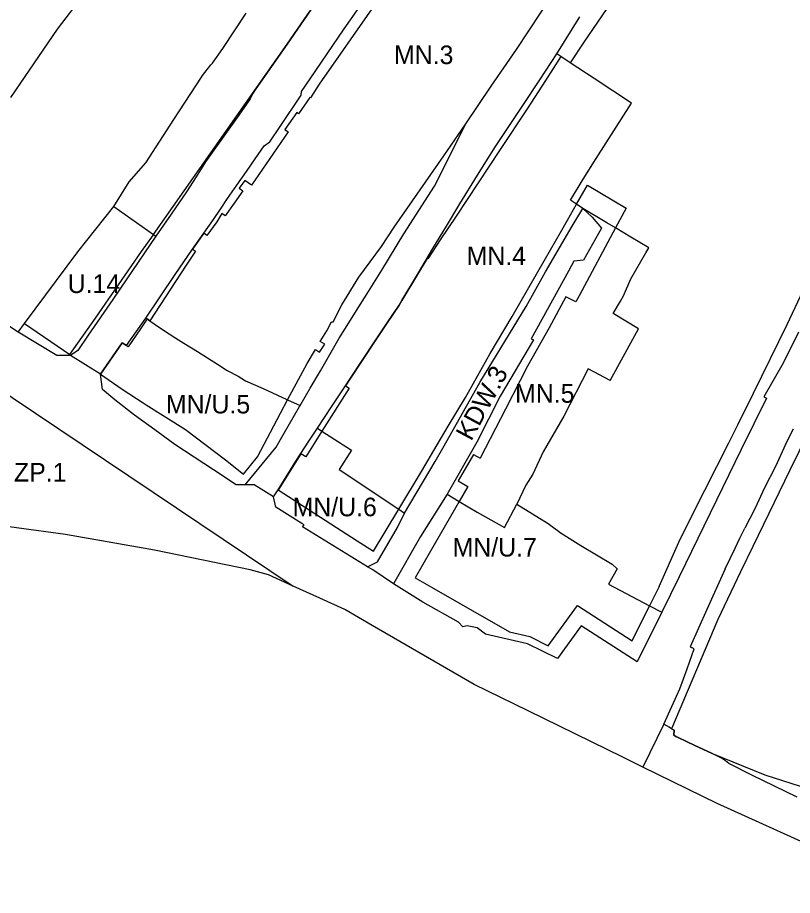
# Model space of a CAD drawing. Extents: x 7425067 to 7426806, y 5549054 to 5550619.
# Drawn here: x 7425448.3 to 7425656.7, y 5549710.3 to 5549946.2 of the extents above; entities that cross this region are included whole.
import ezdxf

# ---------------------------------------------------------------- set-up
doc = ezdxf.new("R2010")
doc.units = 0
for name, color, linetype in [('LIN_Linia Zabudowy Nieprzekraczalna', 7, 'Continuous'), ('LIN_linie_rozgraniczajace', 7, 'Continuous'), ('TXT_Oznaczenia_przeznaczen', 7, 'Continuous')]:
    doc.layers.add(name, color=color, linetype=linetype)

msp = doc.modelspace()

# ---------------------------------------------------------------- linework, layer by layer
at = {"layer": 'LIN_Linia Zabudowy Nieprzekraczalna'}
for points in [[(7425606.5552, 5550040.5472), (7425601.53, 5550033.23), (7425596.51, 5550025.92), (7425591.51, 5550018.64), (7425591.6694, 5550018.5304), (7425591.189, 5550017.8631), (7425586.63, 5550011.53), (7425580.79, 5550003.59), (7425574.84, 5549995.3), (7425575.473, 5549994.8457), (7425546.1246, 5549952.0475), (7425544.2494, 5549949.4263), (7425529.4643, 5549928.2635), (7425527.0756, 5549924.5966), (7425526.94, 5549924.69), (7425523.91, 5549920.31), (7425523.42, 5549920.65), (7425520.23, 5549916.11), (7425521.1342, 5549915.4829), (7425511.2359, 5549901.1957), (7425509.48, 5549902.41)], [(7425484.89, 5549887.86), (7425484.9072, 5549887.8845), (7425520.8, 5549939.01), (7425528.21, 5549949.7), (7425536.13, 5549960.83), (7425537.865, 5549963.3932), (7425543.4, 5549971.57), (7425551.62, 5549983.77), (7425559, 5549994.51), (7425566.23, 5550005.14), (7425570.21, 5550010.81), (7425573.53, 5550015.83), (7425576.29, 5550019.865), (7425579.04, 5550023.905)], [(7425562.96, 5549909.02), (7425568.86, 5549917.69), (7425575.69, 5549927.8), (7425582.5, 5549937.65), (7425585.82, 5549942.63), (7425589.14, 5549947.61), (7425589.3604, 5549947.9398), (7425595.33, 5549956.85), (7425600.34, 5549964.32), (7425605.32, 5549971.85), (7425606.075, 5549973.045), (7425606.83, 5549974.24), (7425608.59, 5549976.71), (7425613.61, 5549984.28), (7425616.08, 5549988.06), (7425618.55, 5549991.84), (7425620.06, 5549994.22), (7425621.56, 5549996.38), (7425626.76, 5550004.31)], [(7425607.9586, 5549950.3857), (7425600.624, 5549939.5493), (7425596.9747, 5549934.0514)], [(7425596.9747, 5549934.0514), (7425594.4146, 5549935.7314), (7425590.31, 5549929.31)], [(7425590.31, 5549929.31), (7425585.42, 5549921.66), (7425578.08, 5549910.74)], [(7425655.2768, 5549863.7294), (7425662.3503, 5549878.7355), (7425665.1746, 5549884.5158), (7425674.3584, 5549902.7629), (7425678.6779, 5549911.0696), (7425680.8016, 5549915.0743), (7425683.7745, 5549920.5636), (7425688.8399, 5549929.4585)], [(7425578.08, 5549910.74), (7425566.3, 5549892.86)], [(7425546.21, 5549884.66), (7425549.63, 5549889.86), (7425562.96, 5549909.02)], [(7425509.48, 5549902.41), (7425507.97, 5549900.35), (7425508.92, 5549899.61), (7425506.59, 5549896.34), (7425504.12, 5549892.89), (7425503.24, 5549893.56), (7425501.88, 5549891.31), (7425499.22, 5549887.64), (7425498.42, 5549888.23), (7425496.91, 5549886.115), (7425495.4, 5549884)], [(7425596.23, 5549891.77), (7425598.6683, 5549896.0411), (7425601.5888, 5549901.157), (7425611.9921, 5549894.9537)], [(7425611.9921, 5549894.9537), (7425609.1429, 5549889.6669), (7425599.32, 5549871.44), (7425598.42, 5549869.77), (7425595.81, 5549871.17)], [(7425556.93, 5549824.24), (7425561.17, 5549831.4), (7425564.1326, 5549836.403), (7425568.75, 5549844.11), (7425575.39, 5549855.96), (7425581.37, 5549865.85), (7425590.35, 5549881.47), (7425594.3076, 5549888.4025), (7425596.23, 5549891.77)], [(7425566.3, 5549892.86), (7425562.02, 5549886.44), (7425558.6225, 5549881.3438)], [(7425450.1963, 5549863.9878), (7425462.43, 5549855.62), (7425469.26, 5549865.41), (7425481.65, 5549883.35), (7425484.89, 5549887.86)], [(7425495.4, 5549884), (7425496.17, 5549883.43), (7425493.67, 5549879.62), (7425483.8994, 5549864.7296)], [(7425530.93, 5549858.45), (7425529.73, 5549859.19), (7425531.49, 5549861.99), (7425532.75, 5549864.44), (7425533.23, 5549864.42), (7425535.51, 5549869.03), (7425540.12, 5549876.43), (7425546.21, 5549884.66)], [(7425558.46, 5549881.44), (7425556.1545, 5549877.6482), (7425555.865, 5549877.165), (7425551.68, 5549870.18), (7425550.95, 5549868.96), (7425547.71, 5549864.135), (7425544.47, 5549859.31), (7425537.71, 5549849.04), (7425536.56, 5549847.28), (7425537.4818, 5549846.5976)], [(7425558.6225, 5549881.3438), (7425558.46, 5549881.44)], [(7425683.144, 5549879.4729), (7425674.6885, 5549862.4106), (7425668.0393, 5549848.9323), (7425663.2786, 5549839.311), (7425655.9796, 5549824.5332), (7425648.9293, 5549809.9832), (7425646.0622, 5549804.0686), (7425642.7058, 5549797.2362), (7425636.6761, 5549784.4652)], [(7425595.81, 5549871.17), (7425591.32, 5549862.78), (7425585.47, 5549852.55), (7425579.51, 5549840.95), (7425572.7321, 5549827.7581)], [(7425483.8994, 5549864.7296), (7425483.2128, 5549865.2121), (7425481.38, 5549862.55), (7425478.0556, 5549857.7212)], [(7425642.0429, 5549836.7222), (7425646.2851, 5549845.2863), (7425655.262, 5549863.6867), (7425655.2768, 5549863.7294)], [(7425478.0556, 5549857.7212), (7425477.6, 5549858.05), (7425476.5, 5549858.76), (7425470.6, 5549850.39)], [(7425493.45, 5549835.54), (7425504.29, 5549827.38), (7425509.12, 5549823.46), (7425512.84, 5549828.17), (7425519.03, 5549839.89), (7425520.9639, 5549843.5063), (7425526.18, 5549853.26), (7425528.45, 5549856.97), (7425529.57, 5549856.27), (7425530.93, 5549858.45)], [(7425470.6, 5549850.39), (7425476.47, 5549846.32), (7425482.11, 5549842.65), (7425482.91, 5549842.17), (7425493.45, 5549835.54)], [(7425537.4818, 5549846.5976), (7425530.1719, 5549835.0691), (7425528.08, 5549831.77), (7425525.81, 5549828.19), (7425524.54, 5549828.95), (7425518.51, 5549819.38)], [(7425626.1923, 5549805.2702), (7425629.9496, 5549812.8357), (7425639.6477, 5549831.8819), (7425642.0429, 5549836.7222)], [(7425570.94, 5549828.8), (7425566.8, 5549821.68)], [(7425570.94, 5549828.8), (7425572.7321, 5549827.7581)], [(7425544.0346, 5549802.8073), (7425550.8242, 5549814.0918), (7425556.93, 5549824.24)], [(7425569.4137, 5549820.2035), (7425569.3949, 5549820.171), (7425567.1006, 5549816.1863), (7425559.41, 5549802.83), (7425555.27, 5549795.64)], [(7425566.8, 5549821.68), (7425569.3949, 5549820.171)], [(7425518.42, 5549819.31), (7425539.7, 5549805.6), (7425544.0346, 5549802.8073)], [(7425620.8453, 5549793.314), (7425626.1923, 5549805.2702)], [(7425555.27, 5549795.64), (7425559.65, 5549793.11), (7425567.02, 5549788.89), (7425580.6308, 5549781.0966)], [(7425620.8453, 5549793.314), (7425618.2934, 5549788.1268)], [(7425591.0582, 5549777.4058), (7425598.9295, 5549788.1676), (7425613.6401, 5549778.6681)], [(7425613.6401, 5549778.6681), (7425618.2934, 5549788.1268)], [(7425636.6761, 5549784.4652), (7425624.1991, 5549755.0945)], [(7425580.6308, 5549781.0966), (7425586.1149, 5549779.8371), (7425591.0582, 5549777.4058)], [(7425624.1991, 5549755.0945), (7425624.94, 5549754.67), (7425624.79, 5549753.35), (7425625.375, 5549753.025), (7425625.96, 5549752.7), (7425630.45, 5549750.59), (7425634.94, 5549748.48), (7425649.28, 5549742.72), (7425658.83, 5549739.66), (7425672.26, 5549735.38), (7425680.88, 5549732.76), (7425701.88, 5549726.85)]]:
    msp.add_lwpolyline(points, dxfattribs=at)
at = {"layer": 'LIN_linie_rozgraniczajace'}
for points in [[(7425472.43, 5549960.77), (7425459.01, 5549943.13)], [(7425528.21, 5549949.7), (7425520.8, 5549939.01)], [(7425536.19, 5549943.2), (7425540.21, 5549948.92)], [(7425585.82, 5549942.63), (7425589.14, 5549947.61)], [(7425503.53, 5549937.93), (7425509.79, 5549947.39)], [(7425593.35, 5549936.43), (7425599.57, 5549946.4)], [(7425459.01, 5549943.13), (7425446.415, 5549924.73)], [(7425531.595, 5549936.465), (7425536.19, 5549943.2)], [(7425582.5, 5549937.65), (7425585.82, 5549942.63)], [(7425520.8, 5549939.01), (7425512.41, 5549927.03)], [(7425500.75, 5549933.94), (7425503.53, 5549937.93)], [(7425527, 5549929.73), (7425531.595, 5549936.465)], [(7425575.69, 5549927.8), (7425582.5, 5549937.65)], [(7425588.775, 5549929.505), (7425593.35, 5549936.43)], [(7425603.4, 5549929.835), (7425596.9747, 5549934.0514), (7425594.4146, 5549935.7314), (7425593.35, 5549936.43)], [(7425498.06, 5549930.65), (7425500.32, 5549933.47)], [(7425500.32, 5549933.47), (7425500.75, 5549933.94)], [(7425490.37, 5549918.8), (7425497.78, 5549930.21)], [(7425497.78, 5549930.21), (7425498.06, 5549930.65)], [(7425525.835, 5549928.025), (7425527, 5549929.73)], [(7425584.2, 5549922.58), (7425588.775, 5549929.505)], [(7425613.45, 5549923.24), (7425603.4, 5549929.835)], [(7425512.41, 5549927.03), (7425511.54, 5549925.72)], [(7425524.67, 5549926.32), (7425525.835, 5549928.025)], [(7425568.86, 5549917.69), (7425575.69, 5549927.8)], [(7425510.91, 5549924.4), (7425507.87, 5549919.98)], [(7425511.54, 5549925.72), (7425510.91, 5549924.4)], [(7425518.98, 5549916.93), (7425524.58, 5549925.38)], [(7425524.58, 5549925.38), (7425524.67, 5549926.32)], [(7425576.83, 5549911.52), (7425584.2, 5549922.58)], [(7425608.68, 5549915.78), (7425613.45, 5549923.24)], [(7425507.87, 5549919.98), (7425503.385, 5549913.695)], [(7425482.79, 5549907.13), (7425490.37, 5549918.8)], [(7425516.16, 5549912.83), (7425518.98, 5549916.93)], [(7425560.44, 5549900.91), (7425568.86, 5549917.69)], [(7425603.91, 5549908.32), (7425608.68, 5549915.78)], [(7425503.385, 5549913.695), (7425498.9, 5549907.41)], [(7425514.62, 5549911.72), (7425516.16, 5549912.83)], [(7425512.24, 5549908.275), (7425514.62, 5549911.72)], [(7425572.05, 5549903.815), (7425576.83, 5549911.52)], [(7425509.86, 5549904.83), (7425512.24, 5549908.275)], [(7425600.45, 5549902.745), (7425603.91, 5549908.32)], [(7425478.38, 5549902.07), (7425482.79, 5549907.13)], [(7425498.9, 5549907.41), (7425496.325, 5549903.395)], [(7425496.325, 5549903.395), (7425493.75, 5549899.38)], [(7425507.34, 5549901.185), (7425509.86, 5549904.83)], [(7425567.27, 5549896.11), (7425572.05, 5549903.815)], [(7425596.99, 5549897.17), (7425600.45, 5549902.745)], [(7425474.22, 5549895.44), (7425478.38, 5549902.07)], [(7425504.82, 5549897.54), (7425507.34, 5549901.185)], [(7425552.23, 5549888.05), (7425560.44, 5549900.91)], [(7425493.75, 5549899.38), (7425489.65, 5549893.405)], [(7425502.9, 5549894.755), (7425504.82, 5549897.54)], [(7425563.66, 5549890.13), (7425567.27, 5549896.11)], [(7425600.35, 5549894.91), (7425598.6683, 5549896.0411), (7425596.99, 5549897.17)], [(7425464.52, 5549883.22), (7425474.22, 5549895.44)], [(7425474.22, 5549895.44), (7425484.9072, 5549887.8845), (7425485.55, 5549887.43)], [(7425489.65, 5549893.405), (7425485.55, 5549887.43)], [(7425500.98, 5549891.97), (7425502.9, 5549894.755)], [(7425597.46, 5549890.14), (7425600.35, 5549894.91)], [(7425600.35, 5549894.91), (7425602.85, 5549892.6)], [(7425606.815, 5549891.055), (7425600.35, 5549894.91)], [(7425498.42, 5549888.23), (7425500.98, 5549891.97)], [(7425602.85, 5549892.6), (7425605.38, 5549889.59)], [(7425613.28, 5549887.2), (7425609.1429, 5549889.6669), (7425606.815, 5549891.055)], [(7425560.05, 5549884.15), (7425563.66, 5549890.13)], [(7425590.3, 5549877.89), (7425597.46, 5549890.14)], [(7425605.38, 5549889.59), (7425600.53, 5549881.02)], [(7425485.55, 5549887.43), (7425477.73, 5549876.01)], [(7425496.91, 5549886.115), (7425498.42, 5549888.23)], [(7425546.28, 5549878.3), (7425552.23, 5549888.05)], [(7425618.14, 5549884.3), (7425613.28, 5549887.2)], [(7425490.75, 5549877.19), (7425495.4, 5549884)], [(7425495.4, 5549884), (7425496.91, 5549886.115)], [(7425555.865, 5549877.165), (7425556.1545, 5549877.6482), (7425560.05, 5549884.15)], [(7425617.28, 5549882.98), (7425618.14, 5549884.3)], [(7425448.47, 5549861.67), (7425450.1963, 5549863.9878), (7425464.52, 5549883.22)], [(7425613.22, 5549875.96), (7425617.28, 5549882.98)], [(7425597.93, 5549880.73), (7425596.47, 5549878.03)], [(7425600.53, 5549881.02), (7425597.93, 5549880.73)], [(7425482.86, 5549865.46), (7425490.75, 5549877.19)], [(7425542.675, 5549872.555), (7425546.28, 5549878.3)], [(7425551.68, 5549870.18), (7425555.865, 5549877.165)], [(7425585.07, 5549868.55), (7425590.3, 5549877.89)], [(7425596.47, 5549878.03), (7425586.49, 5549859.84)], [(7425477.73, 5549876.01), (7425473.925, 5549870.475)], [(7425611.29, 5549871.39), (7425613.22, 5549875.96)], [(7425539.07, 5549866.81), (7425542.675, 5549872.555)], [(7425448.47, 5549861.67), (7425433.63, 5549871.43)], [(7425473.925, 5549870.475), (7425467.31, 5549860.84)], [(7425550.95, 5549868.96), (7425551.68, 5549870.18)], [(7425608.53, 5549866.71), (7425610.49, 5549870.01)], [(7425610.49, 5549870.01), (7425611.29, 5549871.39)], [(7425547.71, 5549864.135), (7425550.95, 5549868.96)], [(7425572.65, 5549848.14), (7425585.07, 5549868.55)], [(7425477.6, 5549858.05), (7425482.86, 5549865.46)], [(7425482.86, 5549865.46), (7425483.2128, 5549865.2121), (7425483.8994, 5549864.7296), (7425485.08, 5549863.9)], [(7425536.955, 5549863.425), (7425539.07, 5549866.81)], [(7425615.36, 5549862.59), (7425608.53, 5549866.71)], [(7425485.08, 5549863.9), (7425487.27, 5549862.35)], [(7425534.84, 5549860.04), (7425536.955, 5549863.425)], [(7425544.47, 5549859.31), (7425547.71, 5549864.135)], [(7425458.92, 5549855.37), (7425448.47, 5549861.67)], [(7425467.31, 5549860.84), (7425464.5, 5549856.74)], [(7425487.27, 5549862.35), (7425490.875, 5549860.045)], [(7425607.66, 5549848.67), (7425615.36, 5549862.59)], [(7425658.37, 5549861.7), (7425654.19, 5549853.35)], [(7425470.6, 5549850.39), (7425476.5, 5549858.76)], [(7425476.5, 5549858.76), (7425477.6, 5549858.05)], [(7425490.875, 5549860.045), (7425493.02, 5549858.68)], [(7425493.02, 5549858.68), (7425496.695, 5549856.435)], [(7425532.3, 5549855.65), (7425534.84, 5549860.04)], [(7425537.71, 5549849.04), (7425544.47, 5549859.31)], [(7425587.04, 5549859.59), (7425578.16, 5549844.45)], [(7425586.49, 5549859.84), (7425587.04, 5549859.59)], [(7425464.5, 5549856.74), (7425462.58, 5549855.42)], [(7425496.695, 5549856.435), (7425502.085, 5549853.045)], [(7425529.76, 5549851.26), (7425532.3, 5549855.65)], [(7425462.58, 5549855.42), (7425458.92, 5549855.37)], [(7425470.6, 5549850.39), (7425462.58, 5549855.42)], [(7425654.19, 5549853.35), (7425649.06, 5549844.26)], [(7425502.085, 5549853.045), (7425504.66, 5549851.36)], [(7425504.66, 5549851.36), (7425507.62, 5549849.83)], [(7425527.05, 5549846.615), (7425529.76, 5549851.26)], [(7425601.82, 5549851.83), (7425595.23, 5549839.09)], [(7425607.66, 5549848.67), (7425601.82, 5549851.83)], [(7425471.16, 5549846.24), (7425470.6, 5549850.39)], [(7425507.62, 5549849.83), (7425509.67, 5549848.61)], [(7425509.67, 5549848.61), (7425514.38, 5549846.5)], [(7425536.56, 5549847.28), (7425537.71, 5549849.04)], [(7425440.5058, 5549848.2743), (7425522.4788, 5549793.4392)], [(7425474.5, 5549843.44), (7425471.16, 5549846.24)], [(7425514.38, 5549846.5), (7425520.78, 5549843.59)], [(7425524.34, 5549841.97), (7425527.05, 5549846.615)], [(7425532.78, 5549841.55), (7425536.56, 5549847.28)], [(7425565.45, 5549835.44), (7425572.65, 5549848.14)], [(7425578.16, 5549844.45), (7425571.87, 5549832.08)], [(7425649.71, 5549843.94), (7425642.97, 5549830.135)], [(7425649.06, 5549844.26), (7425649.71, 5549843.94)], [(7425479.81, 5549839.39), (7425474.5, 5549843.44)], [(7425519.76, 5549834.06), (7425524.15, 5549841.69)], [(7425520.78, 5549843.59), (7425520.9639, 5549843.5063), (7425524.34, 5549841.97)], [(7425524.15, 5549841.69), (7425524.34, 5549841.97)], [(7425529, 5549835.82), (7425532.78, 5549841.55)], [(7425485.235, 5549835.435), (7425479.81, 5549839.39)], [(7425595.23, 5549839.09), (7425589.7, 5549829.51)], [(7425490.66, 5549831.48), (7425485.235, 5549835.435)], [(7425527.96, 5549834.23), (7425528.48, 5549835.025)], [(7425528.48, 5549835.025), (7425529, 5549835.82)], [(7425529, 5549835.82), (7425530.1719, 5549835.0691), (7425538.13, 5549829.97)], [(7425562.72, 5549830.48), (7425565.45, 5549835.44)], [(7425654.89, 5549831.51), (7425656.99, 5549835.695)], [(7425517.86, 5549830.725), (7425519.76, 5549834.06)], [(7425523.15, 5549826.98), (7425526.83, 5549832.67)], [(7425526.83, 5549832.67), (7425527.395, 5549833.45)], [(7425527.395, 5549833.45), (7425527.96, 5549834.23)], [(7425571.87, 5549832.08), (7425563.9, 5549818.09)], [(7425501.05, 5549824.66), (7425490.66, 5549831.48)], [(7425509.5558, 5549820.6408), (7425517.86, 5549830.725)], [(7425538.13, 5549829.97), (7425534.8, 5549824.72)], [(7425560.605, 5549826.87), (7425562.72, 5549830.48)], [(7425642.97, 5549830.135), (7425626.27, 5549795.93)], [(7425654.89, 5549831.51), (7425652.2, 5549825.58)], [(7425589.7, 5549829.51), (7425586.91, 5549823.47)], [(7425518.42, 5549819.31), (7425523.15, 5549826.98)], [(7425552.41, 5549813.04), (7425560.605, 5549826.87)], [(7425652.2, 5549825.58), (7425649.24, 5549819.79)], [(7425507.1265, 5549820.6217), (7425501.05, 5549824.66)], [(7425534.8, 5549824.72), (7425550.8242, 5549814.0918), (7425552.41, 5549813.04)], [(7425586.91, 5549823.47), (7425584.99, 5549820.53)], [(7425509.5558, 5549820.6408), (7425507.1265, 5549820.6217)], [(7425511.985, 5549820.66), (7425509.5558, 5549820.6408)], [(7425517.18, 5549817.37), (7425511.985, 5549820.66)], [(7425584.99, 5549820.53), (7425582.57, 5549815.47)], [(7425517.18, 5549817.37), (7425518.42, 5549819.31)], [(7425563.9, 5549818.09), (7425556.7, 5549806.78)], [(7425563.9, 5549818.09), (7425567.1006, 5549816.1863), (7425571.97, 5549813.29)], [(7425649.24, 5549819.79), (7425646.59, 5549814.17)], [(7425517.81, 5549814.61), (7425517.18, 5549817.37)], [(7425579.26, 5549809.17), (7425582.57, 5549815.47)], [(7425582.57, 5549815.47), (7425591.03, 5549810.23)], [(7425524.77, 5549810.23), (7425517.81, 5549814.61)], [(7425571.97, 5549813.29), (7425579.26, 5549809.17)], [(7425646.59, 5549814.17), (7425643.91, 5549808.95)], [(7425461.2, 5549807.3), (7425421.63, 5549812.69)], [(7425550.47, 5549809.14), (7425552.41, 5549813.04)], [(7425525.38, 5549809.84), (7425524.77, 5549810.23)], [(7425524.96, 5549809.35), (7425525.38, 5549809.84)], [(7425542.4436, 5549798.6194), (7425524.96, 5549809.35)], [(7425545.1105, 5549799.9049), (7425550.47, 5549809.14)], [(7425591.03, 5549810.23), (7425594.52, 5549807.67)], [(7425642.61, 5549806.27), (7425643.91, 5549808.95)], [(7425485.18, 5549803.11), (7425461.2, 5549807.3)], [(7425556.7, 5549806.78), (7425549.39, 5549794.01)], [(7425594.52, 5549807.67), (7425599.8, 5549804.36)], [(7425641.31, 5549803.59), (7425642.61, 5549806.27)], [(7425599.8, 5549804.36), (7425608.25, 5549799.27)], [(7425510.88, 5549797.79), (7425485.18, 5549803.11)], [(7425639.97, 5549800.825), (7425641.31, 5549803.59)], [(7425542.4436, 5549798.6194), (7425545.1105, 5549799.9049)], [(7425608.25, 5549799.27), (7425609.57, 5549798.09)], [(7425638.63, 5549798.06), (7425639.97, 5549800.825)], [(7425515.84, 5549796.48), (7425510.88, 5549797.79)], [(7425543.86, 5549797.75), (7425542.4436, 5549798.6194)], [(7425549.39, 5549794.01), (7425543.86, 5549797.75)], [(7425609.57, 5549798.09), (7425607.24, 5549793.92)], [(7425638.63, 5549798.06), (7425633.7, 5549787.17)], [(7425529.66, 5549790.15), (7425522.4788, 5549793.4392), (7425515.84, 5549796.48)], [(7425626.27, 5549795.93), (7425621.55, 5549786.42)], [(7425557.32, 5549789.08), (7425549.39, 5549794.01)], [(7425607.24, 5549793.92), (7425618.2934, 5549788.1268), (7425621.55, 5549786.42)], [(7425536.34, 5549787.09), (7425529.66, 5549790.15)], [(7425566.9, 5549783.77), (7425557.32, 5549789.08)], [(7425633.7, 5549787.17), (7425629.1869, 5549777.1216)], [(7425543.73, 5549782.83), (7425536.34, 5549787.09)], [(7425621.55, 5549786.42), (7425614.92, 5549773.08)], [(7425571.16, 5549767.01), (7425543.73, 5549782.83)], [(7425568.1, 5549782.51), (7425566.9, 5549783.77)], [(7425569.26, 5549782.77), (7425568.1, 5549782.51)], [(7425571.93, 5549782.22), (7425569.26, 5549782.77)], [(7425599.93, 5549782.76), (7425593.5041, 5549773.9742)], [(7425614.92, 5549773.08), (7425599.93, 5549782.76)], [(7425574.18, 5549780.53), (7425571.93, 5549782.22)], [(7425585.44, 5549777.94), (7425574.18, 5549780.53)], [(7425593.5041, 5549773.9742), (7425585.44, 5549777.94)], [(7425628.385, 5549771.195), (7425630.33, 5549776.55)], [(7425629.1869, 5549777.1216), (7425629.57, 5549776.93)], [(7425630.33, 5549776.55), (7425629.57, 5549776.93)], [(7425626.44, 5549765.84), (7425628.385, 5549771.195)], [(7425585.62, 5549759.93), (7425571.16, 5549767.01)], [(7425624.285, 5549761.06), (7425626.44, 5549765.84)], [(7425611.06, 5549747.45), (7425585.62, 5549759.93)], [(7425622.13, 5549756.28), (7425624.285, 5549761.06)], [(7425622.13, 5549756.28), (7425616.45, 5549744.8)], [(7425623.535, 5549755.475), (7425622.13, 5549756.28)], [(7425624.94, 5549754.67), (7425624.1991, 5549755.0945), (7425623.535, 5549755.475)], [(7425624.79, 5549753.35), (7425624.94, 5549754.67)], [(7425625.375, 5549753.025), (7425624.79, 5549753.35)], [(7425625.96, 5549752.7), (7425625.375, 5549753.025)], [(7425630.45, 5549750.59), (7425625.96, 5549752.7)], [(7425634.94, 5549748.48), (7425630.45, 5549750.59)], [(7425616.45, 5549744.8), (7425611.06, 5549747.45)], [(7425637.82, 5549747.11), (7425634.94, 5549748.48)], [(7425638.71, 5549746.435), (7425637.82, 5549747.11)], [(7425636.47, 5549734.99), (7425616.45, 5549744.8)], [(7425639.6, 5549745.76), (7425638.71, 5549746.435)], [(7425645.79, 5549742.63), (7425639.6, 5549745.76)], [(7425657.99, 5549736.72), (7425645.79, 5549742.63)], [(7425691.12, 5549710.29), (7425636.47, 5549734.99)]]:
    msp.add_lwpolyline(points, dxfattribs=at)

# ---------------------------------------------------------------- texts
at = {"layer": 'TXT_Oznaczenia_przeznaczen'}
for s, p in [('MN.3', (7425549.5658, 5549933.6998)), ('MN.4', (7425569.0961, 5549879.6807)), ('U.14', (7425461.7913, 5549872.1759)), ('MN.5', (7425582.1273, 5549842.6913)), ('MN/U.5', (7425488.225, 5549839.815)), ('ZP.1', (7425447.3644, 5549821.522)), ('MN/U.6', (7425522.2876, 5549812.1863)), ('MN/U.7', (7425565.3216, 5549801.3717))]:
    msp.add_text(s, height=5, dxfattribs=at).set_placement(p)
msp.add_text('KDW.3', height=5, rotation=61.624649, dxfattribs=at).set_placement((7425570.3228, 5549832.1807))

doc.saveas('drawing.dxf')
